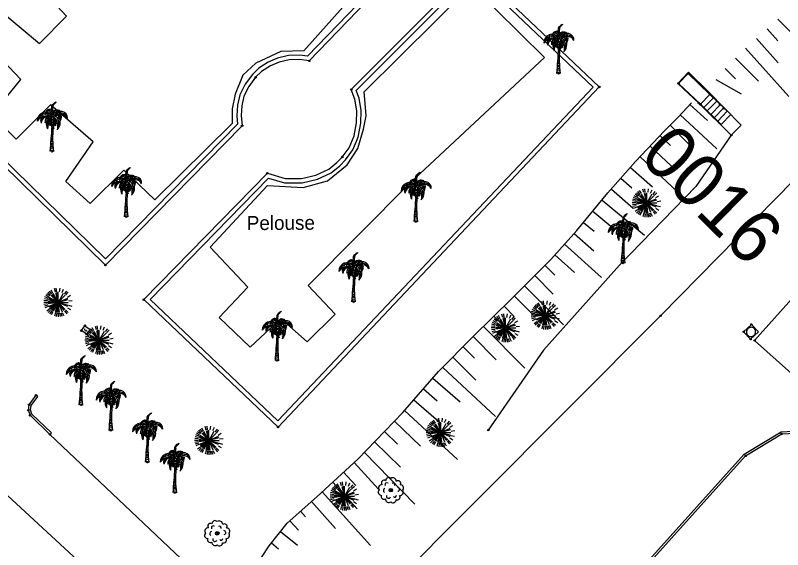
# Model space of a CAD drawing. Extents: x 344013 to 344423, y 298505 to 298795.
# Drawn here: x 344222.4 to 344275.5, y 298714.1 to 298751.1 of the extents above; entities that cross this region are included whole.
import ezdxf

# ---------------------------------------------------------------- set-up
doc = ezdxf.new("R2010")
doc.units = 0
for name, color, linetype in [('Default', 7, 'Continuous'), ('DH_CADRE -CARTOUCHE', 7, 'Continuous'), ('PC_CONCRETE', 7, 'Continuous'), ('PS_BOLT', 7, 'Continuous'), ('PS_CONST', 7, 'Continuous'), ('PS_DIM', 7, 'Continuous'), ('PS_WELD', 7, 'Continuous'), ('TOPO_POINT', 7, 'Continuous'), ('TOPO_TALUS-TERRAIN NATUREL', 7, 'Continuous'), ('VOIRIE_BORDURE', 7, 'Continuous'), ('VOIRIE_ESPACE VERT', 7, 'Continuous')]:
    doc.layers.add(name, color=color, linetype=linetype)

# ---------------------------------------------------------------- blocks, each defined once
blk = doc.blocks.new('PTT3')
at = {"layer": 'Default'}
for p, q in [((0, 1), (1, 1)), ((0, 0), (0, 1)), ((1, 0), (0, 0)), ((1, 1), (1, 0))]:
    blk.add_line(p, q, dxfattribs=at)
for centre, radius, start, end in [((0.5, 0.7), 0.0417, 0, 180), ((0.5, 0.7), 0.0417, 180, 0), ((0.5, 0.29), 0.0417, 0, 180), ((0.5, 0.29), 0.0417, 180, 0), ((0.4, 0.49), 0.229, 297.2754, 62.7246)]:
    blk.add_arc(centre, radius, start, end, dxfattribs=at)
blk = doc.blocks.new('REG_INC')
at = {"layer": 'Default'}
for p, q in [((0, 1), (1, 1)), ((0, 0), (0, 1)), ((1, 1), (1, 0)), ((1, 0), (0, 0))]:
    blk.add_line(p, q, dxfattribs=at)
for centre, start, end in [((0.498, 0.5), 135.00554, 180.00554), ((0.5, 0.498), 90.00577, 135.00577), ((0.5, 0.5), 45.00687, 90.00687), ((0.499, 0.499), 0.00663, 45.00663), ((0.501, 0.5), 180.00663, 225.00663), ((0.499, 0.498), 225.00686, 270.00686), ((0.499, 0.5), 270.00577, 315.00577), ((0.501, 0.499), 315.00554, 0.00554)]:
    blk.add_arc(centre, 0.44, start, end, dxfattribs=at)
blk = doc.blocks.new('POINT_DISPLAY')
at = {"layer": 'Default'}
blk.add_circle((0, 0), 0.05, dxfattribs=at)
blk = doc.blocks.new('COCO')
at = {"layer": 'Default'}
for p, q in [((-0.037, 1.06), (0.056, 1.071)), ((0.058, 1.14), (-0.03, 1.162)), ((-0.026, 1.226), (0.061, 1.212)), ((-0.062, 0.537), (0.046, 0.552)), ((0.047, 0.655), (-0.058, 0.642)), ((-0.046, 0.891), (0.052, 0.927)), ((0.054, 0.998), (-0.041, 0.985)), ((0.046, 0.033), (-0.076, 0.051)), ((-0.073, 0.17), (0.045, 0.209)), ((0.045, 0.292), (-0.07, 0.288)), ((-0.068, 0.371), (0.045, 0.374)), ((0.045, 0.47), (-0.065, 0.453))]:
    blk.add_line(p, q, dxfattribs=at)
for points in [[(0.029, 2.551), (-0.016, 2.896), (0.002, 3.125), (0.059, 3.241), (0.173, 3.348), (0.189, 3.356), (0.282, 3.415), (0.266, 3.373), (0.2, 3.318), (0.143, 3.247), (0.093, 3.2), (0.081, 3.165), (0.057, 3.133), (0.057, 3.099), (0.06, 3.037), (0.039, 2.989), (0.039, 2.944), (0.049, 2.877), (0.037, 2.841), (0.013, 2.736)], [(-0.487, 2.68), (-0.386, 2.65)], [(0.013, 2.736), (0.036, 2.813), (0.046, 2.746)], [(0.196, 2.687), (0.323, 2.715)], [(0.283, 2.765), (0.331, 2.786)], [(-0.746, 2.559), (-0.864, 2.483)], [(-0.77, 2.413), (-0.836, 2.333)], [(-0.607, 2.534), (-0.704, 2.443)], [(-0.636, 2.639), (-0.541, 2.608)], [(-0.421, 2.58), (-0.503, 2.523)], [(-0.183, 2.493), (-0.348, 2.417), (-0.401, 2.307), (-0.448, 2.203), (-0.471, 2.086), (-0.474, 2.023), (-0.466, 1.973), (-0.455, 2.054), (-0.451, 2.146), (-0.387, 2.292), (-0.351, 2.354), (-0.284, 2.404), (-0.233, 2.445), (-0.012, 2.495)], [(-0.256, 2.553), (-0.385, 2.508)], [(-0.276, 2.151), (-0.329, 2.086)], [(-0.203, 2.314), (-0.274, 2.258)], [(-0.23, 2.152), (-0.237, 2.043)], [(-0.161, 2.218), (-0.158, 2.122)], [(-0.04, 2.247), (-0.081, 2.179)], [(0.015, 2.414), (-0.056, 2.352)], [(0.022, 2.24), (0.043, 2.13)], [(0.081, 2.404), (0.106, 2.299)], [(0.133, 2.608), (0.185, 2.634)], [(0.385, 2.37), (0.469, 2.254)], [(-0.321, 1.997), (-0.364, 1.9)], [(-0.059, 2.024), (-0.083, 1.998)], [(-0.025, 2.032), (0.002, 1.954)], [(0.473, 2.115), (0.509, 2.012)], [(-0.055, 0.716), (0.048, 0.717), (0.049, 0.787), (-0.051, 0.795)]]:
    blk.add_lwpolyline(points, dxfattribs=at)
for centre, radius in [((-0.187, 1.897), 0.0384), ((-0.144, 1.978), 0.0616), ((-0.124, 1.896), 0.0376), ((-0.11, 1.84), 0.0471), ((0.134, 1.862), 0.0549), ((0.208, 1.822), 0.0626), ((0.254, 1.938), 0.0628)]:
    blk.add_circle(centre, radius, dxfattribs=at)
for centre, radius, start, end in [((-0.427, 2.113), 0.595, 43.6121, 181.4625), ((-0.123, 2.59), 0.323, 122.3475, 158.7636), ((-0.199, 2.618), 0.238, 4.5218, 154.101), ((-0.252, 2.556), 0.231, 4.2441, 134.2103), ((-0.16, 2.647), 0.255, 21.0861, 122.3475), ((0.376, 2.508), 0.372, 113.7681, 175.3309), ((0.376, 2.508), 0.372, 113.7681, 175.3309), ((0.418, 2.527), 0.326, 97.1248, 183.9512), ((1.025, 2.053), 0.958, 126.6858, 153.1664), ((0.618, 2.316), 0.451, 356.1627, 159.0009), ((0.344, 2.407), 0.451, 69.0817, 104.862), ((-1.005, 1.577), 1.786, 37.5668, 40.5156), ((-0.254, 2.28), 0.869, 28.4725, 37.0965), ((0.493, 2.767), 0.0679, 35.3205, 126.6858), ((-0.054, 2.379), 0.738, 25.8194, 35.3205), ((-0.291, 1.543), 0.918, 76.7389, 142.8025), ((-0.38, 1.964), 0.648, 57.9192, 166.6201), ((-0.3, 2.12), 0.482, 151.1331, 199.5942), ((-0.196, 1.874), 0.565, 78.514, 171.3504), ((-0.32, 2.055), 0.433, 119.0834, 188.7621), ((0.362, 1.922), 0.754, 136.7113, 208.8221), ((0.551, 1.79), 0.879, 137.733, 194.3716), ((0.649, 1.599), 0.949, 145.5146, 182.4528), ((0.62, 2.159), 0.753, 153.0868, 230.1124), ((0.659, 2.068), 0.718, 142.3554, 222.2794), ((-0.007, 2.465), 0.0563, 81.7475, 144.3035), ((-0.189, 1.21), 1.324, 71.3715, 81.7475), ((0.294, 2.595), 0.256, 198.6765, 199.7627), ((0.963, 1.939), 0.9, 143.9866, 203.4288), ((0.544, 1.816), 0.474, 137.1953, 172.8987), ((0.308, 2.014), 0.226, 121.4297, 182.29), ((27.302, 0.106), 27.266, 175.4791, 176.5597), ((0.311, 2.152), 0.219, 141.856, 191.5175), ((0.404, 1.878), 0.354, 125.0585, 146.3893), ((0.398, 2.098), 0.301, 136.4569, 162.0685), ((0.357, 2.084), 0.244, 133.1184, 172.7534), ((-0.759, 1.958), 0.922, 344.8505, 15.8988), ((-0.404, 2.045), 0.619, 329.4666, 26.6793), ((-0.289, 2.11), 0.564, 317.8279, 12.3386), ((0.59, 2.015), 0.548, 29.5654, 139.3517), ((-0.543, 1.744), 0.96, 344.8781, 41.1461), ((-0.341, 1.9), 0.828, 46.9767, 50.1231), ((0.609, 2.187), 0.468, 12.1077, 148.3146), ((-0.157, 2.027), 0.74, 51.2475, 54.5217), ((-0.341, 1.9), 0.828, 334.0687, 41.194), ((-0.157, 2.027), 0.74, 315.1472, 39.0239), ((-1.704, 1.849), 2.327, 7.5978, 16.3666), ((-0.254, 2.28), 0.869, 350.8883, 14.7063), ((-0.482, 2.552), 1.161, 339.3597, 356.5925), ((-85.428, 7.294), 85.622, 355.11326, 356.26352), ((-0.279, 1.637), 0.281, 2.1499, 36.6325), ((-0.265, 1.505), 0.316, 339.9997, 25.7228), ((0.199, 1.66), 0.176, 166.9443, 185.5966), ((0.372, 1.847), 0.277, 133.5956, 173.487), ((0.808, 1.542), 0.777, 142.2358, 156.28), ((0.242, 1.964), 0.147, 110.9727, 165.9756)]:
    blk.add_arc(centre, radius, start, end, dxfattribs=at)
blk.add_ellipse((27.425, 0.272), major_axis=(-27.371, 0.966), ratio=0.529859, start_param=6.255729, end_param=6.369141, dxfattribs=at)
blk = doc.blocks.new('ARB1')
at = {"layer": 'Default'}
blk.add_circle((0, 0), 0.122, dxfattribs=at)
for centre, radius, start, end in [((-0.471, 0.503), 0.183, 53.9554, 222.2066), ((-0.153, 0.664), 0.211, 43.6925, 183.5969), ((0.139, 0.613), 0.241, 358.4583, 125.1928), ((0.501, 0.468), 0.183, 325.1444, 131.0175), ((-0.613, 0.139), 0.241, 88.4583, 215.1928), ((-0.373, -0.024), 0.149, 103.7092, 242.3465), ((-0.276, 0.37), 0.134, 52.4396, 209.5496), ((0.164, 0.38), 0.112, 330.5895, 133.7127), ((0.458, 0.052), 0.137, 276.6214, 88.967), ((0.613, -0.139), 0.241, 268.4583, 35.1928), ((0.664, 0.153), 0.211, 313.6925, 93.5969), ((-0.664, -0.153), 0.211, 133.6925, 273.5969), ((-0.478, -0.443), 0.19, 155.2243, 300.9377), ((-0.163, -0.42), 0.148, 159.5371, 338.1663), ((0.271, -0.38), 0.112, 210.5895, 13.7127), ((0.448, -0.483), 0.188, 243.1323, 33.0297), ((-0.139, -0.613), 0.241, 178.4583, 305.1928), ((0.153, -0.664), 0.211, 223.6925, 3.5969)]:
    blk.add_arc(centre, radius, start, end, dxfattribs=at)
blk = doc.blocks.new('ARB2')
at = {"layer": 'Default'}
for p, q in [((-0.575, 0.453), (-0.775, 0.605)), ((-0.513, 0.525), (-0.688, 0.702)), ((-0.438, 0.589), (-0.588, 0.786)), ((-0.356, 0.642), (-0.481, 0.858)), ((-0.181, 0.716), (-0.244, 0.956)), ((-0.088, 0.736), (-0.119, 0.983)), ((0.106, 0.736), (0.144, 0.983)), ((0.287, 0.684), (0.388, 0.914)), ((0.456, 0.589), (0.612, 0.786)), ((0.531, 0.525), (0.706, 0.702)), ((-0.731, 0), (-0.981, 0)), ((-0.725, 0.1), (-0.969, 0.133)), ((-0.706, 0.195), (-0.944, 0.259)), ((-0.675, 0.286), (-0.9, 0.381)), ((-0.631, 0.373), (-0.844, 0.497)), ((0.65, 0.373), (0.862, 0.497)), ((0.744, 0.1), (0.987, 0.133)), ((-0.725, -0.1), (-0.969, -0.133)), ((-0.706, -0.195), (-0.944, -0.259)), ((-0.675, -0.287), (-0.9, -0.383)), ((-0.575, -0.455), (-0.775, -0.605)), ((-0.513, -0.527), (-0.688, -0.702)), ((0.531, -0.527), (0.706, -0.702)), ((0.65, -0.373), (0.862, -0.498)), ((0.725, -0.195), (0.963, -0.259)), ((-0.438, -0.591), (-0.588, -0.787)), ((-0.356, -0.644), (-0.481, -0.859)), ((-0.181, -0.717), (-0.244, -0.956)), ((-0.088, -0.737), (-0.119, -0.983)), ((0.013, -0.741), (0.013, -0.989)), ((0.106, -0.737), (0.144, -0.983)), ((0.2, -0.717), (0.263, -0.956)), ((0.287, -0.686), (0.388, -0.916)), ((0.456, -0.591), (0.612, -0.787))]:
    blk.add_line(p, q, dxfattribs=at)
for points in [[(-0.688, 0.091), (0.013, 0), (-0.338, 0.608)], [(-0.419, 0.556), (0.013, 0), (-0.638, 0.269)], [(-0.169, 0.677), (0.013, 0), (-0.6, 0.35)], [(0.013, 0.008), (0.013, 0), (-0.081, 0.695)], [(0.362, 0.608), (0.013, 0), (0.013, 0.702)], [(-0.487, -0.497), (0.013, 0), (-0.694, 0)], [(-0.638, -0.269), (0.013, 0), (-0.688, -0.092)], [(-0.487, 0.495), (0.013, 0), (-0.669, 0.181)], [(-0.169, -0.678), (0.013, 0), (-0.6, -0.352)], [(-0.544, -0.428), (0.013, 0), (-0.338, -0.608)], [(-0.081, -0.695), (0.013, 0), (-0.419, -0.558)], [(0.013, -0.702), (0.013, 0), (0, 0)], [(0.656, 0.269), (0.013, 0), (0.506, 0.495)], [(0.688, 0.181), (0.013, 0), (0.713, 0)], [(0.438, -0.558), (0.013, 0), (0.656, -0.269)], [(0.506, -0.497), (0.013, 0), (0.688, -0.181)], [(0.1, -0.695), (0.013, 0), (0.281, -0.648)], [(0.019, 0), (0.013, 0), (0.013, -0.009)]]:
    blk.add_lwpolyline(points, dxfattribs=at)

msp = doc.modelspace()

# ---------------------------------------------------------------- linework, layer by layer
at = {"layer": 'DH_CADRE -CARTOUCHE'}
msp.add_lwpolyline([(344273.541, 298728.568), (344280.403, 298722.45), (344288.5, 298731.494), (344281.65, 298737.626)], close=True, dxfattribs=at)
at = {"layer": 'PS_BOLT'}
msp.add_lwpolyline([(344268.951, 298747.044), (344270.455, 298745.6), (344269.791, 298744.913), (344268.277, 298746.357)], close=True, dxfattribs=at)
at = {"layer": 'PS_DIM'}
for points in [[(344269.696, 298744.985), (344268.227, 298746.364), (344268.969, 298747.134), (344270.359, 298745.771), (344272.612, 298743.479), (344271.934, 298742.772), (344269.696, 298744.985)], [(344270.695, 298745.369), (344270.031, 298744.681)], [(344270.935, 298745.137), (344270.27, 298744.449)], [(344271.174, 298744.906), (344270.51, 298744.218)], [(344271.414, 298744.674), (344270.75, 298743.986)], [(344271.654, 298744.442), (344270.99, 298743.755)], [(344271.894, 298744.211), (344271.229, 298743.523)]]:
    msp.add_lwpolyline(points, dxfattribs=at)
msp.add_lwpolyline([(344270.455, 298745.6), (344271.894, 298744.211), (344271.229, 298743.523), (344269.791, 298744.913)], close=True, dxfattribs=at)
at = {"layer": 'PS_WELD'}
for points in [[(344267.039, 298730.273), (344294.784, 298758.546), (344373.471, 298696.387)], [(344257.544, 298703.725), (344248.073, 298711.237), (344267.039, 298730.273)]]:
    msp.add_lwpolyline(points, dxfattribs=at)
at = {"layer": 'TOPO_TALUS-TERRAIN NATUREL'}
for p, q in [((344275.15, 298750.815), (344276.735, 298749.218)), ((344274.415, 298750.137), (344275.165, 298749.298)), ((344273.669, 298749.471), (344275.168, 298747.793)), ((344272.923, 298748.805), (344275.921, 298745.448)), ((344272.214, 298748.1), (344273.816, 298746.519)), ((344271.512, 298747.387), (344272.233, 298746.676)), ((344270.859, 298746.638), (344272.606, 298745.629)), ((344269.072, 298744.91), (344270.275, 298743.799)), ((344268.393, 298744.175), (344270.932, 298741.831)), ((344267.691, 298743.463), (344268.978, 298742.172)), ((344266.994, 298742.746), (344267.733, 298742.054)), ((344266.31, 298742.016), (344267.788, 298740.631)), ((344265.626, 298741.286), (344268.582, 298738.517)), ((344264.954, 298740.545), (344266.475, 298739.207)), ((344264.293, 298739.794), (344265.054, 298739.125)), ((344263.633, 298739.043), (344265.138, 298737.719)), ((344262.987, 298738.28), (344265.92, 298735.852)), ((344262.349, 298737.509), (344263.742, 298736.356)), ((344261.711, 298736.738), (344262.446, 298736.13)), ((344261.065, 298735.975), (344262.411, 298734.762)), ((344260.395, 298735.232), (344262.951, 298732.929)), ((344259.726, 298734.489), (344261.074, 298733.274)), ((344259.034, 298733.767), (344259.71, 298733.089)), ((344258.326, 298733.061), (344259.61, 298731.772)), ((344257.617, 298732.355), (344260.328, 298729.636)), ((344256.909, 298731.648), (344258.196, 298730.357)), ((344256.199, 298730.944), (344256.912, 298730.224)), ((344255.488, 298730.24), (344256.914, 298728.801)), ((344254.778, 298729.536), (344257.629, 298726.658)), ((344254.067, 298728.832), (344255.652, 298727.233)), ((344253.363, 298728.121), (344254.163, 298727.329)), ((344252.659, 298727.41), (344254.258, 298725.826)), ((344251.955, 298726.7), (344255.616, 298723.291)), ((344251.278, 298725.964), (344253.16, 298724.317)), ((344250.62, 298725.211), (344251.561, 298724.388)), ((344249.961, 298724.458), (344251.843, 298722.812)), ((344249.302, 298723.706), (344252.985, 298720.322)), ((344248.614, 298722.98), (344250.414, 298721.244)), ((344247.92, 298722.26), (344248.82, 298721.392)), ((344247.225, 298721.54), (344249.026, 298719.804)), ((344246.531, 298720.82), (344250.025, 298717.241)), ((344245.822, 298720.115), (344247.514, 298718.273)), ((344245.086, 298719.438), (344245.932, 298718.517)), ((344244.349, 298718.761), (344246.041, 298716.92)), ((344243.612, 298718.084), (344246.967, 298714.375)), ((344242.871, 298717.414), (344244.533, 298715.545)), ((344242.123, 298716.749), (344242.467, 298716.362)), ((344241.376, 298716.084), (344241.964, 298715.423)), ((344240.719, 298715.333), (344241.899, 298714.387)), ((344240.094, 298714.552), (344240.598, 298714.148))]:
    msp.add_line(p, q, dxfattribs=at)
for points in [[(344238.432, 298712.054), (344239.938, 298714.358), (344241.185, 298715.913), (344243.24, 298717.742), (344246.077, 298720.349), (344249.189, 298723.577), (344251.671, 298726.412), (344254.067, 298728.831), (344256.737, 298731.477), (344259.433, 298734.164), (344261.244, 298736.174), (344263.396, 298738.775), (344265.304, 298740.943), (344267.298, 298743.071), (344268.251, 298744.021), (344269.173, 298745.019), (344269.173, 298745.019)], [(344271.934, 298742.772), (344269.476, 298739.229), (344264.188, 298733.769), (344258.926, 298727.897), (344255.104, 298722.358)]]:
    msp.add_lwpolyline(points, dxfattribs=at)
at = {"layer": 'VOIRIE_BORDURE'}
for points in [[(344223.799, 298724.775), (344223.315, 298724.111), (344223.264, 298723.745), (344223.396, 298723.386), (344224.767, 298722.063)], [(344224.767, 298722.063), (344224.872, 298722.17), (344223.525, 298723.47), (344223.418, 298723.762), (344223.458, 298724.053), (344223.92, 298724.686), (344223.799, 298724.775)], [(344257.644, 298703.788), (344266.054, 298713.165), (344272.82, 298720.69), (344275.38, 298722.243), (344279.959, 298722.487), (344280.269, 298722.569)], [(344224.767, 298722.063), (344236.864, 298710.583), (344237.595, 298709.887), (344249.529, 298698.855)], [(344257.755, 298703.688), (344266.166, 298713.064), (344272.917, 298720.574), (344275.425, 298722.095), (344279.982, 298722.338), (344280.403, 298722.45)], [(344221.201, 298718.398), (344241.864, 298699.32), (344247.363, 298694.936)]]:
    msp.add_lwpolyline(points, dxfattribs=at)
at = {"layer": 'VOIRIE_ESPACE VERT'}
for points in [[(344228.609, 298733.786), (344215.617, 298746.488), (344237.992, 298769.574), (344251.389, 298756.925), (344242.713, 298747.917), (344242.041, 298748.012), (344241.328, 298747.986), (344240.625, 298747.821), (344240.024, 298747.565), (344239.421, 298747.187), (344239.008, 298746.783), (344238.537, 298746.143), (344238.196, 298745.471), (344238.047, 298744.807), (344237.999, 298744.129), (344238.073, 298743.423)], [(344228.605, 298734.21), (344216.04, 298746.493), (344238.001, 298769.152), (344250.963, 298756.915), (344242.603, 298748.236), (344242.057, 298748.313), (344241.288, 298748.284), (344240.531, 298748.107), (344239.884, 298747.832), (344239.235, 298747.424), (344238.781, 298746.98), (344238.281, 298746.301), (344237.912, 298745.574), (344237.75, 298744.85), (344237.698, 298744.124), (344237.76, 298743.532)], [(344231.266, 298731.391), (344239.817, 298740.14), (344241.041, 298739.766), (344242.189, 298739.766), (344243.184, 298740.005), (344244.081, 298740.424), (344244.633, 298740.88), (344244.997, 298741.263), (344245.477, 298741.91), (344245.824, 298742.729), (344245.996, 298743.636), (344246.014, 298744.465), (344245.874, 298745.265), (344245.627, 298745.935), (344254.062, 298754.412), (344262.797, 298746.113), (344240.559, 298722.574)], [(344231.694, 298731.399), (344239.904, 298739.8), (344240.996, 298739.466), (344242.225, 298739.466), (344243.284, 298739.721), (344244.243, 298740.168), (344244.838, 298740.66), (344245.227, 298741.07), (344245.739, 298741.76), (344246.112, 298742.642), (344246.295, 298743.605), (344246.314, 298744.487), (344246.165, 298745.344), (344245.975, 298745.86), (344254.068, 298753.992), (344262.373, 298746.102), (344240.547, 298722.999)]]:
    msp.add_lwpolyline(points, close=True, dxfattribs=at)
for points in [[(344246.971, 298753.819), (344242.349, 298748.612), (344240.741, 298748.564), (344239.017, 298747.758), (344238.114, 298746.921), (344237.581, 298745.614), (344237.388, 298744.601), (344237.388, 298743.588)], [(344221.506, 298751.241), (344224.052, 298749.112), (344225.913, 298751.013), (344223.58, 298753.527)], [(344246.524, 298745.78), (344253.955, 298753.169), (344258.996, 298748.148), (344249.672, 298739.461), (344242.635, 298732.378), (344244.519, 298730.394), (344242.565, 298728.46), (344240.743, 298730.084), (344238.616, 298728.105), (344236.471, 298730.146), (344238.473, 298732.251), (344235.868, 298735.019), (344239.835, 298739.286), (344242.288, 298739.15), (344243.975, 298739.62), (344245.332, 298740.713), (344246.081, 298741.85), (344246.468, 298743.19), (344246.662, 298744.121), (344246.579, 298744.964), (344246.524, 298745.78)], [(344237.388, 298743.588), (344232.031, 298738.31), (344229.88, 298740.35), (344227.563, 298738.056), (344225.874, 298739.577), (344227.767, 298742.312), (344224.814, 298744.88), (344222.418, 298742.507), (344220.739, 298744.193), (344222.741, 298746.629), (344219.835, 298749.685)]]:
    msp.add_lwpolyline(points, dxfattribs=at)

# ---------------------------------------------------------------- block references
at = {"layer": 'PC_CONCRETE', "xscale": 0.7061365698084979, "yscale": 0.7435896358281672, "rotation": -47.08152000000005}
msp.add_blockref('REG_INC', (344272.785, 298729.165), dxfattribs=at)
at = {"layer": 'PS_BOLT', "xscale": 0.42120983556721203, "yscale": 0.43583991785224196, "rotation": -125.89128000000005}
msp.add_blockref('PTT3', (344227.189, 298729.587), dxfattribs=at)
at = {"layer": 'TOPO_POINT'}
for p in [(344242.713, 298747.917), (344259.972, 298747.053), (344268.951, 298747.044), (344239.008, 298746.783), (344268.277, 298746.357), (344245.627, 298745.935), (344262.797, 298746.113), (344270.455, 298745.6), (344269.696, 298744.985), (344269.791, 298744.913), (344271.16, 298744.88), (344271.41, 298744.634), (344238.073, 298743.423), (344271.934, 298742.772), (344224.904, 298741.657), (344244.997, 298741.263), (344239.817, 298740.14), (344266.062, 298738.086), (344230.046, 298737.133), (344250.096, 298736.798), (344228.609, 298733.786), (344264.441, 298733.93), (344225.325, 298731.198), (344231.266, 298731.391), (344245.786, 298731.242), (344259.055, 298730.317), (344267.039, 298730.273), (344227.189, 298729.587), (344256.295, 298729.428), (344273.329, 298729.672), (344226.942, 298729.246), (344227.302, 298728.999), (344272.785, 298729.165), (344228.165, 298728.587), (344273.265, 298728.648), (344273.541, 298728.568), (344240.487, 298727.175), (344223.799, 298724.775), (344223.315, 298724.111), (344226.913, 298724.105), (344223.264, 298723.745), (344223.396, 298723.386), (344240.559, 298722.574), (344224.767, 298722.063), (344228.978, 298722.34), (344251.803, 298722.192), (344255.104, 298722.358), (344275.425, 298722.095), (344235.76, 298721.645), (344272.917, 298720.574), (344231.504, 298720.138), (344248.369, 298718.207), (344233.412, 298718.033), (344245.136, 298717.788), (344236.348, 298715.218)]:
    msp.add_blockref('POINT_DISPLAY', p, dxfattribs=at)
at = {"layer": 'VOIRIE_ESPACE VERT'}
for name, p in [('COCO', (344259.972, 298747.053)), ('COCO', (344224.904, 298741.657)), ('COCO', (344230.046, 298737.133)), ('COCO', (344250.096, 298736.798)), ('ARB2', (344266.062, 298738.086)), ('COCO', (344264.441, 298733.93)), ('COCO', (344245.786, 298731.242)), ('ARB2', (344225.325, 298731.198)), ('ARB2', (344259.055, 298730.317)), ('COCO', (344240.487, 298727.175)), ('ARB2', (344256.295, 298729.428)), ('ARB2', (344228.165, 298728.587)), ('COCO', (344226.913, 298724.105)), ('COCO', (344228.978, 298722.34)), ('COCO', (344231.504, 298720.138)), ('ARB2', (344251.803, 298722.192)), ('ARB2', (344235.76, 298721.645)), ('COCO', (344233.412, 298718.033)), ('ARB2', (344245.136, 298717.788)), ('ARB1', (344248.369, 298718.207)), ('ARB1', (344236.348, 298715.218))]:
    msp.add_blockref(name, p, dxfattribs=at)

# ---------------------------------------------------------------- texts
at = {"layer": 'PS_CONST'}
for s, height, rotation, p in [('0016', 3.662, 315.3665, (344265.462, 298741.207)), ('Pelouse', 0.9758, 0.3665, (344238.397, 298736.201))]:
    msp.add_text(s, height=height, rotation=rotation, dxfattribs=at).set_placement(p)

doc.saveas('drawing.dxf')
